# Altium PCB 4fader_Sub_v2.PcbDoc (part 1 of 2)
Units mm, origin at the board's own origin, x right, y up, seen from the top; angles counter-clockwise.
Board outline 100 x 45 mm, 2 copper layers (Top Layer, Bottom Layer); 98 components, 50 nets, 488 pads, 159 vias.
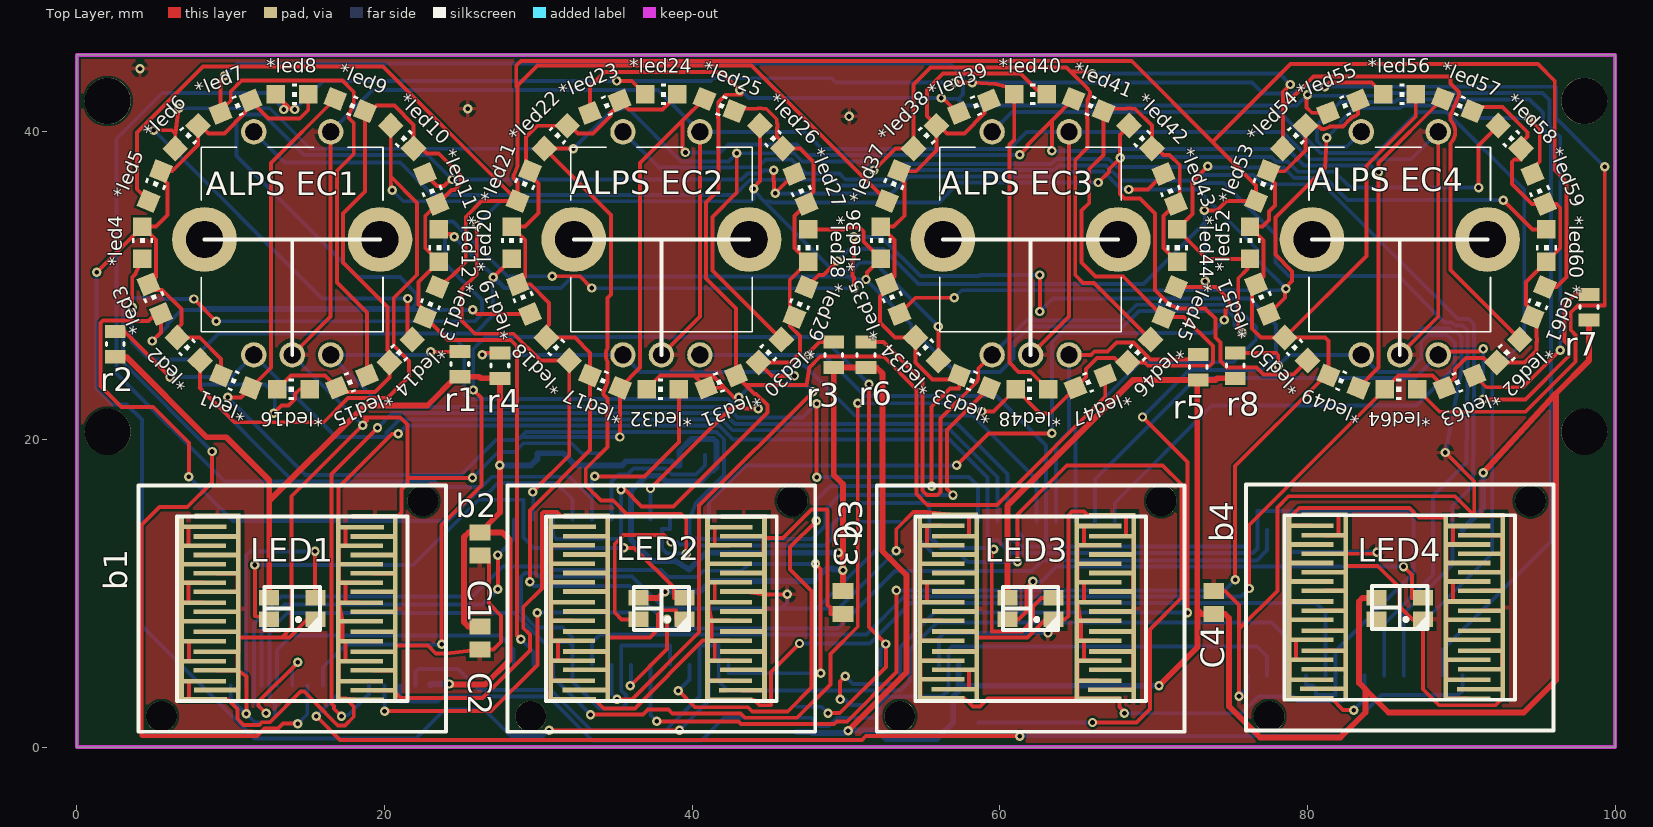
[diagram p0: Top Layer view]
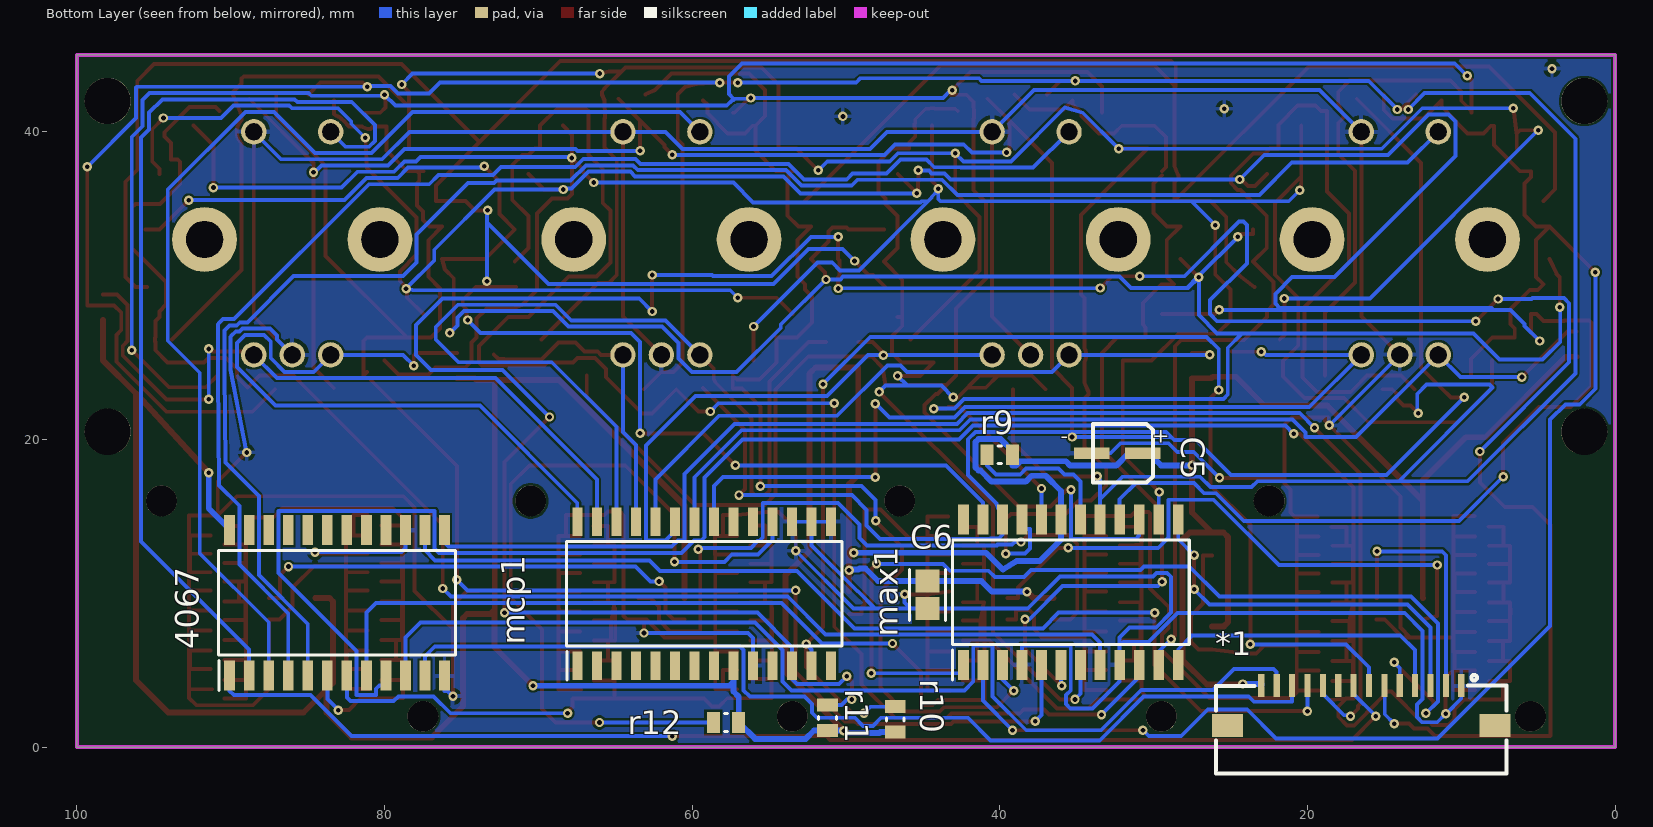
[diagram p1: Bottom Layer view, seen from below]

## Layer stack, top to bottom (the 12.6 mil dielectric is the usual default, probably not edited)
Top Solder: solder mask 0.0102, Solder Resist, Dk 3.5
Top Layer: signal copper 0.0356
Dielectric 1: dielectric 0.32, FR-4, Dk 4.8
Bottom Layer: signal copper 0.0356
Bottom Solder: solder mask 0.0102, Solder Resist, Dk 3.5

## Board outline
0,0 100,0 100,45 0,45

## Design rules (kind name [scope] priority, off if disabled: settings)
Clearance [All] p1: gap=0.152 ignorepadtopadclearanceinfootprint=FALSE
ComponentClearance [All] p1: gap=0.254 collisioncheckmode=3 verticalgap=2540 showdistances=FALSE donotcheckwithout3dbody=TRUE
Height [All] p1: minheight=0 maxheight=254 prefheight=12.7
HoleSize [All] p1: absolutevalues=TRUE maxlimit=25.4 minlimit=0.025 maxpercent=80.000 minpercent=20.000
MinimumSolderMaskSliver [All] p1: minsoldermaskwidth=0.076
PolygonConnect [All] p1: connectstyle=Relief reliefconductorwidth=0.254 reliefentries=4 polygonreliefangle="90 Angle" airgapwidth=0.254
RoutingVias [All] p1: holewidth=0.305 width=0.61 viastyle="Through Hole" minholewidth=0.254 minwidth=0.254 maxholewidth=0.711 maxwidth=1.27
SilkToSilkClearance [All] p1: silktosilkclearance=0
SilkToSolderMaskClearance [IsPad] p1: minsilkscreentomaskgap=0 clearancetoexposedcopper=TRUE
SolderMaskExpansion [All] p1: expansion=0.102 istentingtop=FALSE
SupplyNets "Schematic Supply Nets_1" [InNet('GND')] p1: voltage=0.000
SupplyNets "Schematic Supply Nets" [InNet('+5')] p2: voltage=0.000
Width Width_1 [InNet('+5')] p1: maxlimit=0.508 minlimit=0.254 preferedwidth=0.381
Width [All] p2: maxlimit=0.254 minlimit=0.254 preferedwidth=0.254
24 further rules are at their usual default settings.

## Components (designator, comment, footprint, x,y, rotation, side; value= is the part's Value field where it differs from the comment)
4067 "74HCT4067D,112" SOIC127P1032X265-24N 83.085,9.375 r90 bottom
*1 "trans" FPC-SMD_KH-FG1.0-H2.0-14PIN 16.5,1.586 r180 bottom
*led1 "led1210" 1210贴片led 10.3,23.7 r337.5 top
*led2 "led1210" 1210贴片led 7.213,25.835 r315 top
*led3 "led1210" 1210贴片led 5,29.1 r292.5 top
*led4 "led1210" 1210贴片led 4.2,32.8 r270 top
*led5 "led1210" 1210贴片led 5,36.5 r247.5 top
*led6 "led1210" 1210贴片led 7.1,39.7 r225 top
*led7 "led1210" 1210贴片led 10.3,41.7 r202.5 top
*led8 "led1210" 1210贴片led 14,42.5 r180 top
*led9 "led1210" 1210贴片led 17.8,41.8 r157.5 top
*led10 "led1210" 1210贴片led 21.2,39.7 r135 top
*led11 "led1210" 1210贴片led 23.1,36.3 r112.5 top
*led12 "led1210" 1210贴片led 23.6,32.6 r90 top
*led13 "led1210" 1210贴片led 23.1,28.9 r67.5 top
*led14 "led1210" 1210贴片led 21.1,25.7 r45 top
*led15 "led1210" 1210贴片led 17.9,23.7 r22.5 top
*led16 "led1210" 1210贴片led 14.075,23.2 r0 top
*led17 "led1210" 1210贴片led 34.3,23.7 r337.5 top
*led18 "led1210" 1210贴片led 31.213,25.835 r315 top
*led19 "led1210" 1210贴片led 29,29.1 r292.5 top
*led20 "led1210" 1210贴片led 28.2,32.8 r270 top
*led21 "led1210" 1210贴片led 29,36.5 r247.5 top
*led22 "led1210" 1210贴片led 31.1,39.7 r225 top
*led23 "led1210" 1210贴片led 34.3,41.7 r202.5 top
*led24 "led1210" 1210贴片led 38,42.5 r180 top
*led25 "led1210" 1210贴片led 41.8,41.8 r157.5 top
*led26 "led1210" 1210贴片led 45.2,39.7 r135 top
*led27 "led1210" 1210贴片led 47.1,36.3 r112.5 top
*led28 "led1210" 1210贴片led 47.6,32.6 r90 top
*led29 "led1210" 1210贴片led 47.1,28.9 r67.5 top
*led30 "led1210" 1210贴片led 45.1,25.7 r45 top
*led31 "led1210" 1210贴片led 41.9,23.7 r22.5 top
*led32 "led1210" 1210贴片led 38.075,23.2 r0 top
*led33 "led1210" 1210贴片led 58.3,23.7 r337.5 top
*led34 "led1210" 1210贴片led 55.213,25.835 r315 top
*led35 "led1210" 1210贴片led 53,29.1 r292.5 top
*led36 "led1210" 1210贴片led 52.2,32.8 r270 top
*led37 "led1210" 1210贴片led 53,36.5 r247.5 top
*led38 "led1210" 1210贴片led 55.1,39.7 r225 top
*led39 "led1210" 1210贴片led 58.3,41.7 r202.5 top
*led40 "led1210" 1210贴片led 62,42.5 r180 top
*led41 "led1210" 1210贴片led 65.8,41.8 r157.5 top
*led42 "led1210" 1210贴片led 69.2,39.7 r135 top
*led43 "led1210" 1210贴片led 71.1,36.3 r112.5 top
*led44 "led1210" 1210贴片led 71.6,32.6 r90 top
*led45 "led1210" 1210贴片led 71.1,28.9 r67.5 top
*led46 "led1210" 1210贴片led 69.1,25.7 r45 top
*led47 "led1210" 1210贴片led 65.9,23.7 r22.5 top
*led48 "led1210" 1210贴片led 62.075,23.2 r0 top
*led49 "led1210" 1210贴片led 82.3,23.7 r337.5 top
*led50 "led1210" 1210贴片led 79.213,25.835 r315 top
*led51 "led1210" 1210贴片led 77,29.1 r292.5 top
*led52 "led1210" 1210贴片led 76.2,32.8 r270 top
*led53 "led1210" 1210贴片led 77,36.5 r247.5 top
*led54 "led1210" 1210贴片led 79.1,39.7 r225 top
*led55 "led1210" 1210贴片led 82.3,41.7 r202.5 top
*led56 "led1210" 1210贴片led 86,42.5 r180 top
*led57 "led1210" 1210贴片led 89.8,41.8 r157.5 top
*led58 "led1210" 1210贴片led 93.2,39.7 r135 top
*led59 "led1210" 1210贴片led 95.1,36.3 r112.5 top
*led60 "led1210" 1210贴片led 95.6,32.6 r90 top
*led61 "led1210" 1210贴片led 95.1,28.9 r67.5 top
*led62 "led1210" 1210贴片led 93.1,25.7 r45 top
*led63 "led1210" 1210贴片led 89.9,23.7 r22.5 top
*led64 "led1210" 1210贴片led 86.075,23.2 r0 top
"ALPS EC1" "PEC11H-4125F-S0020" "ALPS EC11" 14,25.5 r0 top
"ALPS EC2" "PEC11H-4125F-S0020" "ALPS EC11" 38,25.5 r0 top
"ALPS EC3" "PEC11H-4125F-S0020" "ALPS EC11" 62,25.5 r0 top
"ALPS EC4" "PEC11H-4125F-S0020" "ALPS EC11" 86,25.5 r0 top
b1 "button" BUTTON 14,9 r180 top
b2 "button" BUTTON 38,9 r180 top
b3 "button" BUTTON 62,9 r180 top
b4 "button" BUTTON 86,9.075 r180 top
C1 "GRM21BR71A106KE51L" CAPC2013X140X45LL15T25 26.2,13.2 r90 top
C2 "GRM21BR71A106KE51L" CAPC2013X140X45LL15T25 26.2,7.1 r270 top
C3 "GRM21BR71A106KE51L" CAPC2013X140X45LL15T25 49.8,9.4 r90 top
C4 "GRM21BR71A106KE51L" CAPC2013X140X45LL15T25 73.9,9.4 r90 top
C5 "10uF" "ELECTROLYTIC CAPACITOR SMD 4X5.4" 34.329,19.1 r90 bottom
C6 "0.1uf" FP-CC0805-0_85-IPC_A 44.7,9.9 r90 bottom value="100 nF"
LED1 "ws2812" ws2812 14,9 r0 top
LED2 "ws2812" ws2812 38,9 r0 top
LED3 "ws2812" ws2812 62,9 r0 top
LED4 "ws2812" ws2812 86,9 r0 top
max1 "MAX7219CWG" SOIC127P1032X265-24N 35.385,10.075 r90 bottom
mcp1 "MCP23017T-E_SO" SOIC127P1030X265-28N 59.215,9.975 r90 bottom
r1 "SG73S2ATTD1101F" RESC2013X60X30LL20T20 24.9,24.9 r270 top
r2 "SG73S2ATTD1101F" RESC2013X60X30LL20T20 2.5,26.2 r270 top
r3 "SG73S2ATTD1101F" RESC2013X60X30LL20T20 49.2,25.5 r270 top
r4 "SG73S2ATTD1101F" RESC2013X60X30LL20T20 27.5,24.8 r270 top
r5 "SG73S2ATTD1101F" RESC2013X60X30LL20T20 72.9,24.7 r270 top
r6 "SG73S2ATTD1101F" RESC2013X60X30LL20T20 51.3,25.5 r270 top
r7 "SG73S2ATTD1101F" RESC2013X60X30LL20T20 98.3,28.6 r270 top
r8 "SG73S2ATTD1101F" RESC2013X60X30LL20T20 75.3,24.8 r270 top
r9 "10k" RESC2013X60X30LL20T20 40,19 r180 bottom
r10 "SG73S2ATTD1101F" RESC2013X60X30LL20T20 46.8,1.8 r270 bottom
r11 "SG73S2ATTD1101F" RESC2013X60X30LL20T20 51.2,1.9 r270 bottom
r12 "SG73S2ATTD1101F" RESC2013X60X30LL20T20 57.8,1.6 r180 bottom

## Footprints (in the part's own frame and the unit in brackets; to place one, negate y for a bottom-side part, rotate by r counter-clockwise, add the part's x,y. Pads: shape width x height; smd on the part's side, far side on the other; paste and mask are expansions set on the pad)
1210贴片led [mm]
  rect 1.2x1.2 smd paste+0 mask+0.051: 1(-1.041,0.064) 2(1.059,0.064)
  silkscreen extent -0.29,-0.61 0.01,0.74, body extent -0.99,-0.56 1.01,0.69, height 0.8
"ALPS EC11" [mm]
  round 1.65 hole 1.1 slot 1.1 at 0 deg paste-2539.97 mask+0.051: A1(-2.5,0) B1(2.5,0) C1(0,0) S1(-2.5,14.5) W1(2.5,14.5)
  round 4.215 hole 2.4 paste-2539.97 mask+0.051: MH1(-5.7,7.5) MH2(5.7,7.5)
  silkscreen extent -5.9,0 5.9,13.5
BUTTON [mm]
  rect 0.3x12 smd paste+0 mask+0.102: 1(-3,0) 1(7.2,0) 2(-6.7,0) 2(3.5,0)
  silkscreen extent -10,-8 10,8
CAPC2013X140X45LL15T25 [mm] "Chip Capacitor, 2-Leads, Body 2.00x1.25mm, IPC High Density"
  rect 1.05x1.35 smd: 1(-0.75,0) 2(0.75,0)
  body extent -1.08,-0.7 1.07,0.7, height 1.4
"ELECTROLYTIC CAPACITOR SMD 4X5.4" [mm]
  rect 0.75x2.3 smd paste+0 mask+0.102: 1(0,-3.629) 2(0,-0.308)
  silkscreen extent -1.91,-4.27 1.9,-0.38
FP-CC0805-0_85-IPC_A [mm]
  rect 1.505x1.556 smd paste+0 mask+0: 1(-0.901,0) 2(0.901,0)
  silkscreen extent -1.65,-1.18 1.65,1.18, body extent -1,-0.63 1,0.63, height 0.95
FPC-SMD_KH-FG1.0-H2.0-14PIN [mm]
  rect 0.4x1.5 smd paste+0 mask+0.05: 1(6.5,2.414) 2(5.5,2.414) 3(4.5,2.414) 4(3.5,2.414) 5(2.5,2.414) 6(1.5,2.414) 7(0.5,2.414) 8(-0.5,2.414) 9(-1.5,2.414) 10(-2.5,2.414) 11(-3.5,2.414) 12(-4.5,2.414) 13(-5.5,2.414) 14(-6.5,2.414)
  rect 2x1.5 smd paste+0 mask+0.05: 15(-8.7,-0.186) 16(8.7,-0.186)
  silkscreen extent -9.46,-3.29 9.45,3.1, body extent -9.53,-2.9 9.53,3.1, height 2
RESC2013X60X30LL20T20 [mm] "Chip Resistor, 2-Leads, Body 2.00x1.25mm, IPC High Density"
  rect 0.85x1.35 smd: 1(-0.825,0) 2(0.825,0)
  silkscreen extent -0.1,-0.57 0.1,0.58, body extent -1.1,-0.72 1.1,0.72, height 0.6
SOIC127P1030X265-28N [mm]
  rect 1.85x0.65 smd: 1(-4.675,8.255) 2(-4.675,6.985) 3(-4.675,5.715) 4(-4.675,4.445) 5(-4.675,3.175) 6(-4.675,1.905) 7(-4.675,0.635) 8(-4.675,-0.635) 9(-4.675,-1.905) 10(-4.675,-3.175) 11(-4.675,-4.445) 12(-4.675,-5.715) 13(-4.675,-6.985) 14(-4.675,-8.255) 15(4.675,-8.255) 16(4.675,-6.985) 17(4.675,-5.715) 18(4.675,-4.445) 19(4.675,-3.175) 20(4.675,-1.905) 21(4.675,-0.635) 22(4.675,0.635) 23(4.675,1.905) 24(4.675,3.175) 25(4.675,4.445) 26(4.675,5.715) 27(4.675,6.985) 28(4.675,8.255)
  silkscreen extent -5.6,-8.95 3.4,8.95, body extent -5.15,-8.95 5.15,8.95, height 2.65
SOIC127P1032X265-24N [mm]
  rect 1.95x0.7 smd: 1(-4.725,6.985) 2(-4.725,5.715) 3(-4.725,4.445) 4(-4.725,3.175) 5(-4.725,1.905) 6(-4.725,0.635) 7(-4.725,-0.635) 8(-4.725,-1.905) 9(-4.725,-3.175) 10(-4.725,-4.445) 11(-4.725,-5.715) 12(-4.725,-6.985) 13(4.725,-6.985) 14(4.725,-5.715) 15(4.725,-4.445) 16(4.725,-3.175) 17(4.725,-1.905) 18(4.725,-0.635) 19(4.725,0.635) 20(4.725,1.905) 21(4.725,3.175) 22(4.725,4.445) 23(4.725,5.715) 24(4.725,6.985)
  silkscreen extent -5.7,-7.7 3.4,7.7, body extent -5.17,-7.7 5.17,7.7, height 2.54
ws2812 [mm]
  rect 1.3x1 smd paste+0 mask+0.102: 1(1.5,-0.7) 2(1.5,0.7) 3(-1.5,0.7) 4(-1.5,-0.7)
  silkscreen extent -1.75,-1.4 1.75,1.4

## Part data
4067: "Integrated Circuit", Manufacturer_Name=Nexperia, Mouser Part Number=771-74HCT4067D
C1 C2 C3 C4: library part CMP-2007-03395-1, Manufacturer=Murata
C5: library part "4.3 X 4.3 ELECTROLYTIC  CAPACITOR SMD μF"
C6: library part CMP-1036-04410-2, "CAP CER 0.1UF 25V X7R 0805", Capacitance="100 nF", Manufacturer=Yageo, Manufacturer Part Number=CC0805KRX7R8BB104, Package=CC0805-0.85, Temperature="-30°C to +85°C", Temperature Characteristic=X7R, Temperature Range High=+85°C, Temperature Range Low=-30°C, Tolerance=0.1, Voltage Rating="25 V"
max1: "Integrated Circuit", Manufacturer_Name="Analog Devices", Mouser Part Number=700-MAX7219CWG-NR
mcp1: "Integrated Circuit", Arrow Part Number=MCP23017T-E/SO, Manufacturer_Name=Microchip, Mouser Part Number=579-MCP23017T-E/SO
r1 r2 r3 r4 r5 r6 r7 r8 r10 r11 r12: library part CMP-2001-02660-1, Manufacturer="KOA Speer"
r9: library part CMP-2001-02660-1, Manufacturer="KOA Speer", Part Number=SG73S2ATTD1101F

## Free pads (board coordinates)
  rect 3x0.3 smd paste+0 mask+0.102: 9(8.249,3.098) 9(18.46,3.073) 9(32.252,3.098) 9(42.438,3.073) 9(56.204,3.175) 9(66.415,3.149) 9(80.207,3.175) 9(90.393,3.149) 10(8.191,4.291) 10(18.391,4.291) 10(32.194,4.317) 10(42.394,4.317) 10(56.204,4.419) 10(66.397,4.317) 10(80.2,4.367) 10(90.4,4.367) 11(8.191,5.591) 11(18.391,5.591) 11(32.194,5.617) 11(42.394,5.617) 11(56.197,5.617) 11(66.397,5.617) 11(80.2,5.667) 11(90.4,5.667) 12(8.191,6.891) 12(18.391,6.891) 12(32.194,6.917) 12(42.394,6.917) 12(56.197,6.917) 12(66.397,6.917) 12(80.2,6.967) 12(90.4,6.967) 13(8.191,8.191) 13(18.391,8.191) 13(32.194,8.217) 13(42.394,8.217) 13(56.197,8.217) 13(66.397,8.217) 13(80.2,8.267) 13(90.4,8.267) 14(8.191,9.391) 14(18.391,9.391) 14(32.194,9.417) 14(42.394,9.417) 14(56.197,9.417) 14(66.397,9.417) 14(80.2,9.467) 14(90.4,9.467) 15(8.191,10.691) 15(18.391,10.691) 15(32.194,10.717) 15(42.394,10.717) 15(56.197,10.717) 15(66.397,10.717) 15(80.2,10.767) 15(90.4,10.767) 16(8.191,11.891) 16(18.391,11.891) 16(32.194,11.917) 16(42.394,11.917) 16(56.197,11.917) 16(66.397,11.917) 16(80.2,11.967) 16(90.4,11.967) 17(8.191,13.091) 17(18.391,13.091) 17(32.194,13.117) 17(42.394,13.117) 17(56.197,13.117) 17(66.397,13.117) 17(80.2,13.167) 17(90.4,13.167) 18(8.242,14.324) 18(18.453,14.299) 18(32.245,14.324) 18(42.43,14.299) 18(56.197,14.4) 18(66.408,14.375) 18(80.2,14.4) 18(90.385,14.375) 19(9.142,15.024) 19(19.353,14.999) 19(33.145,15.024) 19(43.352,14.986) 19(57.097,15.1) 19(67.308,15.075) 19(81.1,15.1) 19(91.307,15.062) 20(9.091,13.691) 20(19.291,13.691) 20(33.094,13.717) 20(43.294,13.717) 20(57.097,13.717) 20(67.297,13.717) 20(81.1,13.767) 20(91.3,13.767) 21(9.091,12.491) 21(19.291,12.491) 21(33.094,12.517) 21(43.294,12.517) 21(57.097,12.517) 21(67.297,12.517) 21(81.1,12.567) 21(91.3,12.567) 22(9.091,11.291) 22(19.291,11.291) 22(33.094,11.317) 22(43.294,11.317) 22(57.097,11.317) 22(67.297,11.317) 22(81.1,11.367) 22(91.3,11.367) 23(9.091,10.091) 23(19.291,10.091) 23(33.094,10.117) 23(43.294,10.117) 23(57.097,10.117) 23(67.297,10.117) 23(81.1,10.167) 23(91.3,10.167) 24(9.091,8.791) 24(19.291,8.791) 24(33.094,8.817) 24(43.294,8.817) 24(57.097,8.817) 24(67.297,8.817) 24(81.1,8.867) 24(91.3,8.867) 25(9.091,7.491) 25(19.291,7.491) 25(33.094,7.517) 25(43.294,7.517) 25(57.097,7.517) 25(67.297,7.517) 25(81.1,7.567) 25(91.3,7.567) 26(9.091,6.191) 26(19.291,6.191) 26(33.094,6.217) 26(43.294,6.217) 26(57.097,6.217) 26(67.297,6.217) 26(81.1,6.267) 26(91.3,6.267) 27(9.091,4.991) 27(9.113,3.708) 27(19.273,3.683) 27(19.291,4.991) 27(33.065,3.708) 27(33.094,5.017) 27(43.25,3.683) 27(43.294,5.017) 27(57.068,3.759) 27(57.097,5.017) 27(67.228,3.733) 27(67.297,5.017) 27(81.02,3.784) 27(81.1,5.067) 27(91.206,3.759) 27(91.3,5.067)
  round 2 hole 2: 28(5.5,2) 28(22.5,16) 28(29.5,2) 28(46.5,16) 28(53.5,2) 28(70.5,16) 28(77.5,2) 28(94.5,16)
  round 3 hole 3: 29(2,20.5) 29(2,42) 29(98,20.5) 29(98,42)

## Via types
v1: diameter 0.61, hole 0.305, Top Layer to Bottom Layer, 159 vias

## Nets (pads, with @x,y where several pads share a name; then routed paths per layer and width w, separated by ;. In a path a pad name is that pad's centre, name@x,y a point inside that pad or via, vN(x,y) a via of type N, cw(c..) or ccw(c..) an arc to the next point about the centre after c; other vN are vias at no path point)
+5: 4067.24 *1.14 C1.2 C2.1 C3.2 C4.1 C5.1 C6.2 LED1.3 LED2.3 LED3.3 LED4.3 max1.19 mcp1.9 r1.2 r2.2 r3.2 r4.2 r5.2 r6.2 r7.2 r8.2 r9.2 r10.2 r11.2 r12.2 | length 323.8
  Top Layer w0.381: r2.2@2.5,25.375 3.2,25.375 8.429,20.146 9.712,20.146 12.51,17.348 12.51,16.015 ; LED1.3@12.5,9.7 12.51,9.7 12.51,16.015 ; v1(24.2,4.1) 24.236,4.064 26.531,4.064 28.131,5.664 28.131,13.475 27.656,13.95 C1.2@26.2,13.95 ; C2.1@26.2,7.85 25.437,7.85 25.159,8.128 25.159,13.645 25.464,13.95 C1.2@26.2,13.95 ; LED2.3@36.5,9.7 37.831,9.7 v1(38.237,10.106) ; v1(49.492,12.636) 49.8,12.636 ; C3.2@49.8,10.15 v1(49.8,11.5) 49.8,12.636 ; v1(50.136,1.067) 53.937,4.869 53.937,11.176 52.363,12.751 52.363,24.294 51.982,24.675 r6.2@51.3,24.675 r3.2@49.2,24.675 49.2,17.694 49.8,17.094 49.8,12.636 ; LED3.3@60.5,9.7 60.491,9.7 60.491,15.697 68.668,23.875 r5.2@72.835,23.875 ; v1(70.346,3.988) 72.848,6.49 72.848,8.928 ; r8.2@75.3,23.975 74.129,23.975 74.029,23.875 r5.2@72.9,23.875 r5.2@72.835,23.875 ; LED4.3@84.5,9.7 83.579,9.7 83.351,9.471 83.351,4.175 83.77,3.756 83.77,3.746 ; v1(91.428,17.831) 96.152,22.98 ; r7.2@98.3,27.775 98.311,27.775 98.311,25.139 96.152,22.98 ; 12.51,16.015 18.707,22.212 22.789,22.212 24.651,24.075 r1.2@24.9,24.075 26.15,24.075 26.25,23.975 r4.2@27.5,23.975 v1(27.5,18.313) 27.5,15.25 C1.2@26.2,13.95 ; r5.2@72.835,23.875 72.835,9.525 72.835,8.941 72.848,8.928 ; 72.848,8.928 73.126,8.65 C4.1@73.9,8.65 74.638,8.65 74.905,8.383 74.905,2.646 76.916,0.635 82.151,0.635 83.77,2.254 83.77,3.746 ; 83.77,3.746 85.266,2.25 94.059,2.25 96.152,4.343 96.152,22.98
  Bottom Layer w0.381: *1.14@23,4 23,4.09 23.009,4.1 v1(24.2,4.1) ; v1(27.5,18.313) 29.528,18.313 29.934,18.72 29.934,19.1 C5.1@30.7,19.1 31.631,19.1 32.436,18.295 35.417,18.295 35.702,18.58 38.672,18.58 38.957,18.295 39.175,18.295 39.175,19.25 39.943,20.018 41.392,20.018 41.593,19.817 41.593,18.183 41.392,17.982 41.262,17.982 40.537,17.258 38.32,17.258 37.938,17.64 37.011,17.64 36.02,16.65 max1.19@36.02,14.8 36.02,13.487 37.417,12.09 38.901,12.09 39.79,11.532 40.895,12.636 v1(49.492,12.636) ; v1(38.237,10.106) 40.504,10.106 41.199,10.801 C6.2@44.7,10.801 47.919,10.801 48.733,11.615 49.114,11.615 49.185,11.544 49.756,11.544 v1(49.8,11.5) ; r10.2@46.8,0.975 47.774,0.975 47.84,0.909 49.978,0.909 v1(50.136,1.067) 50.144,1.075 r11.2@51.2,1.075 52.075,1.075 52.617,0.533 55.908,0.533 r12.2@56.975,1.6 56.975,3.277 57.31,3.612 57.31,4.247 ; mcp1.9@57.31,5.3 57.31,4.247 ; v1(70.346,3.988) 57.57,3.988 57.31,4.247 ; 4067.24@90.07,14.1 90.07,14.148 91.428,15.506 v1(91.428,17.831)
b0: 4067.9 b1.1 pad.9@8.249,3.098 pad.9@18.46,3.073 pad.10@8.191,4.291 pad.10@18.391,4.291 pad.11@8.191,5.591 pad.11@18.391,5.591 pad.12@8.191,6.891 pad.12@18.391,6.891 pad.13@8.191,8.191 pad.13@18.391,8.191 pad.14@8.191,9.391 pad.14@18.391,9.391 pad.15@8.191,10.691 pad.15@18.391,10.691 pad.16@8.191,11.891 pad.16@18.391,11.891 pad.17@8.191,13.091 pad.17@18.391,13.091 pad.18@8.242,14.324 pad.18@18.453,14.299 | length 174.1
  Top Layer w0.254: b1.1@6.8,9 6.818,8.161 b1.1@6.846,6.891 ; pad.10@8.191,4.291 pad.10@7.278,4.291 ; pad.11@8.191,5.591 pad.11@7.278,5.591 ; pad.12@8.191,6.891 pad.12@7.278,6.891 ; pad.13@8.191,8.191 b1.1@6.846,8.191 ; pad.14@8.191,9.391 pad.14@7.252,9.391 ; pad.15@8.191,10.691 pad.15@7.252,10.691 ; pad.16@8.191,11.891 b1.1@6.846,11.891 ; pad.17@8.191,13.091 pad.17@7.252,13.091 ; pad.18@8.242,14.324 7.252,14.324 pad.17@7.252,13.091 ; pad.10@18.391,4.291 17.031,4.291 17.031,5.591 pad.11@17.463,5.591 ; pad.11@18.391,5.591 pad.11@17.463,5.591 ; pad.12@18.391,6.891 pad.12@17.463,6.891 ; pad.13@18.391,8.191 pad.13@17.26,8.191 ; pad.14@18.391,9.391 pad.14@17.463,9.391 ; pad.15@18.391,10.691 pad.15@17.463,10.691 ; pad.16@18.391,11.891 b1.1@17.031,11.891 ; pad.17@18.391,13.091 pad.17@17.463,13.091 ; pad.18@18.453,14.299 17.463,14.299 pad.17@17.463,13.091 ; pad.9@18.46,3.073 pad.9@17.492,3.15 ; v1(20.901,20.361) 20.495,20.361 17,16.866 b1.1@17,9 17,8.191 b1.1@17,6.891 ; b1.1@6.846,6.891 pad.12@7.278,6.891 ; b1.1@6.846,6.891 b1.1@6.846,8.191 ; b1.1@6.846,8.191 6.846,9.391 pad.14@7.252,9.391 ; b1.1@6.846,11.891 6.846,13.091 pad.17@7.252,13.091 ; b1.1@6.846,11.891 6.846,10.691 pad.15@7.252,10.691 ; pad.14@7.252,9.391 pad.15@7.252,10.691 ; pad.10@7.278,4.291 7.278,3.098 pad.9@8.249,3.098 9.818,3.098 10.432,2.484 10.432,1.843 10.828,1.448 11.859,1.448 12.027,1.616 12.542,1.616 14.545,3.619 14.778,3.619 16.142,2.254 16.142,2.232 16.958,1.416 17.442,1.416 18,1.974 18,2.642 pad.9@17.492,3.15 ; pad.10@7.278,4.291 6.846,4.291 6.846,5.591 pad.11@7.278,5.591 ; pad.11@7.278,5.591 pad.12@7.278,6.891 ; b1.1@17,6.891 pad.12@17.26,6.891 ; b1.1@17,6.891 17,5.591 17,4.291 17,3.15 pad.9@17.492,3.15 ; b1.1@17.031,11.891 17.031,10.691 pad.15@17.463,10.691 ; b1.1@17.031,11.891 17.031,13.091 pad.17@17.463,13.091 ; pad.12@17.26,6.891 pad.12@17.463,6.891 ; pad.12@17.26,6.891 pad.13@17.26,8.191 ; pad.13@17.26,8.191 17.102,9.019 17.079,9.141 17.031,9.391 pad.14@17.463,9.391 ; pad.11@17.463,5.591 pad.12@17.463,6.891 ; pad.14@17.463,9.391 pad.15@17.463,10.691
  Bottom Layer w0.254: v1(20.901,20.361) 21.435,20.894 41.755,20.894 42.659,19.99 56.726,19.99 59.195,17.52 59.195,13.64 59.398,13.437 59.891,13.437 60.704,12.624 76.467,12.624 76.741,12.897 76.741,15.354 86.881,15.354 86.901,15.335 86.901,11.328 81.809,6.237 81.809,3.396 80.551,3.396 80.551,3.791 80.328,4.013 79.91,4.013 4067.9@79.91,4.65
b1: 4067.8 b2.1 pad.9@32.252,3.098 pad.9@42.438,3.073 pad.10@32.194,4.317 pad.10@42.394,4.317 pad.11@32.194,5.617 pad.11@42.394,5.617 pad.12@32.194,6.917 pad.12@42.394,6.917 pad.13@32.194,8.217 pad.13@42.394,8.217 pad.14@32.194,9.417 pad.14@42.394,9.417 pad.15@32.194,10.717 pad.15@42.394,10.717 pad.16@32.194,11.917 pad.16@42.394,11.917 pad.17@32.194,13.117 pad.17@42.394,13.117 pad.18@32.245,14.324 pad.18@42.43,14.299 | length 120.1
  Top Layer w0.254: pad.10@32.194,4.317 30.849,4.317 30.849,5.617 pad.11@31.281,5.617 ; pad.11@32.194,5.617 pad.11@31.281,5.617 ; pad.12@32.194,6.917 pad.12@31.281,6.917 ; pad.13@32.194,8.217 b2.1@30.849,8.217 ; pad.14@32.194,9.417 30.849,9.417 b2.1@30.849,8.217 ; pad.15@32.194,10.717 30.849,10.717 b2.1@30.849,11.917 ; pad.16@32.194,11.917 b2.1@30.849,11.917 ; pad.17@32.194,13.117 pad.17@31.179,13.117 ; pad.18@32.245,14.324 30.8,14.324 b2.1@30.8,13.132 ; b2.1@41,9 41,8.217 b2.1@41,6.917 ; pad.10@42.394,4.317 41.034,4.317 41.034,5.617 pad.11@41.466,5.617 ; pad.11@42.394,5.617 pad.11@41.466,5.617 ; pad.12@42.394,6.917 pad.12@41.466,6.917 ; pad.13@42.394,8.217 pad.13@41.263,8.217 ; pad.14@42.394,9.417 pad.14@41.466,9.417 ; pad.15@42.394,10.717 pad.15@41.466,10.717 ; pad.16@42.394,11.917 b2.1@41.034,11.917 ; pad.17@42.394,13.117 pad.17@41.466,13.117 ; pad.18@42.43,14.299 41.466,14.299 pad.17@41.466,13.117 ; v1(46.979,6.731) 45.129,4.882 45.129,2.72 44.385,2.72 44.032,3.073 pad.9@42.438,3.073 41,3.073 b2.1@41,6.917 ; b2.1@30.8,6.917 b2.1@30.849,6.917 ; b2.1@30.8,6.917 30.8,8.217 b2.1@30.8,9 30.8,9.417 30.8,10.717 30.8,11.917 30.8,13.117 b2.1@30.8,13.132 ; b2.1@30.8,6.917 30.8,5.617 30.8,3.608 30.544,3.352 30.798,3.098 pad.9@32.252,3.098 33.668,3.098 34.252,2.515 36.279,2.515 40.681,6.917 b2.1@41,6.917 ; b2.1@30.8,13.132 31.179,13.132 pad.17@31.179,13.117 ; b2.1@30.849,6.917 b2.1@30.849,8.217 ; b2.1@30.849,6.917 pad.12@31.281,6.917 ; b2.1@30.849,11.917 30.849,13.117 pad.17@31.179,13.117 ; pad.11@31.281,5.617 pad.12@31.281,6.917 ; b2.1@41,6.917 pad.12@41.263,6.917 ; b2.1@41.034,11.917 41.034,13.117 pad.17@41.466,13.117 ; b2.1@41.034,11.917 41.034,10.717 pad.15@41.466,10.717 ; pad.12@41.263,6.917 pad.13@41.263,8.217 ; pad.12@41.263,6.917 pad.12@41.466,6.917 ; pad.13@41.263,8.217 41.11,9.021 41.082,9.167 41.034,9.417 pad.14@41.466,9.417 ; pad.11@41.466,5.617 pad.12@41.466,6.917 ; pad.14@41.466,9.417 pad.15@41.466,10.717
  Bottom Layer w0.254: v1(46.979,6.731) 51.55,6.731 54.191,9.373 80.545,9.373 81.18,8.738 4067.8@81.18,4.65
b2: 4067.7 b3.1 pad.9@56.204,3.175 pad.9@66.415,3.149 pad.10@56.204,4.419 pad.10@66.397,4.317 pad.11@56.197,5.617 pad.11@66.397,5.617 pad.12@56.197,6.917 pad.12@66.397,6.917 pad.13@56.197,8.217 pad.13@66.397,8.217 pad.14@56.197,9.417 pad.14@66.397,9.417 pad.15@56.197,10.717 pad.15@66.397,10.717 pad.16@56.197,11.917 pad.16@66.397,11.917 pad.17@56.197,13.117 pad.17@66.397,13.117 pad.18@56.197,14.4 pad.18@66.408,14.375 | length 80.9
  Top Layer w0.254: b3.1@54.8,9 54.8,8.217 b3.1@54.8,6.917 ; pad.11@56.197,5.617 b3.1@54.852,5.617 ; pad.12@56.197,6.917 b3.1@54.852,6.917 ; pad.13@56.197,8.217 b3.1@54.852,8.217 ; pad.14@56.197,9.417 pad.14@55.258,9.417 ; pad.15@56.197,10.717 pad.15@55.258,10.717 ; pad.16@56.197,11.917 b3.1@54.852,11.917 ; pad.17@56.197,13.117 pad.17@55.258,13.117 ; pad.18@56.197,14.4 55.258,14.4 pad.17@55.258,13.117 ; pad.10@56.204,4.419 b3.1@54.852,4.419 ; b3.1@65,9 65,6.917 pad.12@65.266,6.917 ; pad.10@66.397,4.317 b3.1@65.063,4.317 ; pad.11@66.397,5.617 pad.11@65.469,5.617 ; pad.12@66.397,6.917 pad.12@65.469,6.917 ; pad.13@66.397,8.217 pad.13@65.266,8.217 ; pad.14@66.397,9.417 pad.14@65.469,9.417 ; pad.15@66.397,10.717 pad.15@65.469,10.717 ; pad.16@66.397,11.917 b3.1@65.037,11.917 ; pad.17@66.397,13.117 pad.17@65.469,13.117 ; pad.18@66.408,14.375 65.469,14.375 pad.17@65.469,13.117 ; v1(68.1,2.2) 68.1,2.296 67.788,2.608 67.788,3.126 67.765,3.149 b3.1@65.063,3.149 ; b3.1@54.8,6.917 b3.1@54.852,6.917 ; b3.1@54.8,6.917 54.8,5.617 b3.1@54.852,5.617 ; b3.1@54.852,4.419 b3.1@54.852,5.617 ; b3.1@54.852,4.419 54.852,3.175 pad.9@56.204,3.175 57.722,3.175 58.255,2.642 58.712,2.642 59.22,3.149 b3.1@65.063,3.149 ; b3.1@54.852,6.917 b3.1@54.852,8.217 ; b3.1@54.852,8.217 54.852,9.417 pad.14@55.258,9.417 ; b3.1@54.852,11.917 54.852,13.117 pad.17@55.258,13.117 ; b3.1@54.852,11.917 54.852,10.717 pad.15@55.258,10.717 ; pad.14@55.258,9.417 pad.15@55.258,10.717 ; b3.1@65.037,11.917 65.037,13.117 pad.17@65.469,13.117 ; b3.1@65.037,11.917 65.037,10.717 pad.15@65.469,10.717 ; b3.1@65.063,3.149 b3.1@65.063,4.317 ; b3.1@65.063,4.317 65.038,5.59 65.037,5.617 pad.11@65.469,5.617 ; pad.12@65.266,6.917 pad.12@65.469,6.917 ; pad.12@65.266,6.917 pad.13@65.266,8.217 ; pad.13@65.266,8.217 65.113,9.021 65.085,9.167 65.037,9.417 pad.14@65.469,9.417 ; pad.11@65.469,5.617 pad.12@65.469,6.917 ; pad.14@65.469,9.417 pad.15@65.469,10.717
  Bottom Layer w0.254: v1(68.1,2.2) 75.704,2.2 76.806,3.302 79.101,3.302 79.414,2.989 82.216,2.989 82.45,3.223 4067.7@82.45,4.65
b3: 4067.6 b4.1 pad.9@80.207,3.175 pad.9@90.393,3.149 pad.10@80.2,4.367 pad.10@90.4,4.367 pad.11@80.2,5.667 pad.11@90.4,5.667 pad.12@80.2,6.967 pad.12@90.4,6.967 pad.13@80.2,8.267 pad.13@90.4,8.267 pad.14@80.2,9.467 pad.14@90.4,9.467 pad.15@80.2,10.767 pad.15@90.4,10.767 pad.16@80.2,11.967 pad.16@90.4,11.967 pad.17@80.2,13.167 pad.17@90.4,13.167 pad.18@80.2,14.4 pad.18@90.385,14.375 | length 83.4
  Top Layer w0.254: pad.10@80.2,4.367 78.855,4.367 78.855,5.667 pad.11@79.261,5.667 ; pad.11@80.2,5.667 pad.11@79.261,5.667 ; pad.12@80.2,6.967 pad.12@79.261,6.967 ; pad.13@80.2,8.267 b4.1@78.855,8.267 ; pad.14@80.2,9.467 78.855,9.467 b4.1@78.855,8.267 ; pad.15@80.2,10.767 78.855,10.767 b4.1@78.855,11.967 ; pad.16@80.2,11.967 b4.1@78.855,11.967 ; pad.17@80.2,13.167 pad.17@79.185,13.167 ; pad.18@80.2,14.4 b4.1@78.8,14.4 ; v1(83,2.4) 82.982,2.418 82.314,2.418 81.58,3.152 80.23,3.152 pad.9@80.207,3.175 78.8,3.175 78.8,4.367 78.8,5.667 b4.1@78.8,6.967 ; pad.18@90.385,14.375 89.472,14.375 pad.17@89.472,13.167 ; pad.9@90.393,3.149 89,3.149 b4.1@89,5.667 ; pad.10@90.4,4.367 89.04,4.367 b4.1@89.04,5.667 ; pad.11@90.4,5.667 b4.1@89.04,5.667 ; pad.12@90.4,6.967 b4.1@89.04,6.967 ; pad.13@90.4,8.267 b4.1@89.04,8.267 ; pad.14@90.4,9.467 pad.14@89.472,9.467 ; pad.15@90.4,10.767 pad.15@89.472,10.767 ; pad.16@90.4,11.967 b4.1@89.04,11.967 ; pad.17@90.4,13.167 pad.17@89.472,13.167 ; b4.1@78.8,6.967 b4.1@78.8,9.075 78.8,9.467 78.8,10.767 78.8,11.967 78.8,13.167 b4.1@78.8,13.183 ; b4.1@78.8,6.967 b4.1@78.855,6.967 ; b4.1@78.8,13.183 79.185,13.183 pad.17@79.185,13.167 ; b4.1@78.8,13.183 b4.1@78.8,14.4 ; b4.1@78.8,14.4 78.8,14.88 79.465,15.545 86.627,15.545 87.237,14.935 89,14.935 89,11.967 b4.1@89,9.075 89,8.267 b4.1@89,6.967 ; b4.1@78.855,6.967 b4.1@78.855,8.267 ; b4.1@78.855,6.967 pad.12@79.261,6.967 ; b4.1@78.855,11.967 78.855,13.167 pad.17@79.185,13.167 ; pad.11@79.261,5.667 pad.12@79.261,6.967 ; b4.1@89,5.667 b4.1@89.04,5.667 ; b4.1@89,5.667 b4.1@89,6.967 ; b4.1@89,6.967 b4.1@89.04,6.967 ; b4.1@89.04,6.967 b4.1@89.04,8.267 ; b4.1@89.04,8.267 89.04,9.467 pad.14@89.472,9.467 ; b4.1@89.04,11.967 89.04,13.167 pad.17@89.472,13.167 ; b4.1@89.04,11.967 89.04,10.767 pad.15@89.472,10.767 ; pad.14@89.472,9.467 pad.15@89.472,10.767
  Bottom Layer w0.254: v1(83,2.4) 83.72,3.12 4067.6@83.72,4.65
b4: 4067.5 "ALPS EC1.S1" | length 111.9
  Bottom Layer w0.254: 11.5,40 13.501,37.998 21.019,37.998 23.127,35.89 42.764,35.89 43.758,36.884 49.241,36.884 49.626,36.5 52.89,36.5 53.903,37.513 63.54,37.513 63.847,37.821 66.91,37.821 67.901,36.83 72.722,36.83 72.89,36.662 74.578,36.662 77.913,33.327 77.913,31.496 78.796,30.613 85.91,30.613 88.91,27.613 89.41,27.613 89.605,27.417 90.082,27.417 90.342,27.156 90.417,27.082 90.417,25.542 cw(c88.5,25.5) 90.417,25.458 90.417,24.367 90.342,18.5 88.171,16.329 88.171,11.191 84.99,8.01 4067.5@84.99,4.65
b5: 4067.4 "ALPS EC2.S1" | length 86.7
  Bottom Layer w0.254: 35.5,40 37.831,37.668 42.543,37.668 42.572,37.697 44.263,37.697 44.768,38.202 46.454,38.202 47.365,37.291 49.566,37.291 49.951,36.906 52.722,36.906 53.735,37.919 63.371,37.919 63.679,38.227 67.079,38.227 67.602,37.704 72.423,37.704 72.946,37.18 76.504,37.18 77.091,36.592 81.005,36.592 89.774,27.823 90.488,27.823 90.749,27.563 90.823,27.488 90.824,25.501 cw(c88.5,25.5) 90.824,25.495 90.823,24.199 90.749,16.999 89.441,15.691 89.441,11.872 86.26,8.692 4067.4@86.26,4.65
b6: 4067.3 "ALPS EC3.S1" | length 73.8
  Bottom Layer w0.254: 59.5,40 60.793,41.294 78.172,41.294 80.841,38.624 84.51,38.624 87.186,41.3 89.041,41.3 94.095,36.246 94.095,26.416 92.012,24.333 92.012,12.595 87.53,8.113 4067.3@87.53,4.65
b7: 4067.2 "ALPS EC4.S1" | length 59.9
  Bottom Layer w0.254: 83.5,40 82.53,39.031 81.01,39.031 80.633,39.408 80.633,40.437 82.131,41.935 85.666,41.935 85.843,42.113 94.444,42.113 95.307,41.25 95.307,40.139 95.828,39.618 95.828,13.366 88.8,6.338 4067.2@88.8,4.65
c1_1: *led1.2 *led9.2 *led17.2 *led25.2 *led33.2 *led41.2 *led49.2 *led57.2 max1.22 | length 198
  Top Layer w0.254: v1(9.818,22.733) 10.682,22.733 *led1.2@11.303,23.354 12.612,24.662 12.612,37.961 *led9.2@16.797,42.146 ; v1(35.303,20.161) *led17.2@35.303,23.354 36.615,24.665 36.615,37.964 39.383,40.732 ; v1(39.561,38.659) 39.383,38.837 39.383,40.732 ; *led25.2@40.797,42.146 39.383,40.732 ; v1(56.96,16.383) 56.554,16.789 56.554,20.604 *led33.2@59.303,23.354 ; v1(61.303,38.503) 61.804,39.004 61.804,39.153 63.386,40.735 ; v1(63.386,38.76) 63.386,40.735 ; *led41.2@64.797,42.146 63.386,40.735 ; *led49.2@83.303,23.354 84.621,24.671 v1(84.621,37.363) 84.621,37.97 *led57.2@88.797,42.146
  Bottom Layer w0.254: v1(9.818,22.733) 14.865,17.686 24.981,17.686 27.25,19.954 28.658,19.954 28.864,20.161 ; v1(35.303,20.161) 28.864,20.161 ; v1(39.561,38.659) 41.822,38.659 42.347,39.184 46.801,39.184 47.505,38.481 61.281,38.481 v1(61.303,38.503) ; v1(56.96,16.383) 49.619,16.383 48.654,15.418 48.654,14.402 47.791,13.538 40.628,13.538 40.602,13.564 40.069,13.564 39.83,13.803 max1.22@39.83,14.8 40.224,15.839 42.063,17.678 42.063,20.012 41.587,20.488 29.191,20.488 28.864,20.161 ; v1(63.386,38.76) 67.462,38.76 67.588,38.886 78.704,38.886 79.778,37.812 84.099,37.812 84.547,37.363 v1(84.621,37.363)
c1_2: *led2.2 *led10.2 *led18.2 *led26.2 *led34.2 *led42.2 *led50.2 *led58.2 max1.14 | length 191.4
  Top Layer w0.254: *led2.2@8.007,25.131 8.007,23.35 10.241,21.116 16.049,21.116 17.615,22.682 20.181,22.682 21.6,24.101 21.6,25.098 20.6,26.098 20.6,29.198 22.111,30.709 22.111,35.382 20.406,37.087 ; *led10.2@20.406,40.404 20.406,37.087 ; v1(20.5,36.2) 20.432,36.268 20.432,36.606 20.406,36.632 20.406,37.087 ; v1(25.997,33.934) 25.997,30.734 25.007,29.743 25.007,27.737 25.87,26.873 28.385,26.873 30.127,25.131 *led18.2@32.007,25.131 32.007,18.964 v1(29.63,16.586) ; v1(44,36.3) 44,36.396 44.406,36.802 *led26.2@44.406,40.404 ; *led34.2@56.007,25.131 v1(56.007,27.343) ; v1(66.4,36.7) 67.091,37.391 67.091,37.563 v1@67.806,38.278 ; v1@67.806,38.302 67.806,39.804 *led42.2@68.406,40.404 ; v1(67.83,38.302) v1@67.806,38.278 ; *led50.2@80.007,25.131 79.092,24.216 77.153,24.216 76.69,24.679 74.75,24.679 74.334,25.096 74.334,26.315 74.016,26.633 74.016,27.851 73.442,28.426 73.367,28.5 71.609,28.5 71.585,28.524 71.074,28.736 70.092,29.718 70.092,34.687 69.117,35.662 68.111,35.662 67.806,35.966 v1@67.806,38.278 ; v1(91.123,36.373) 91.123,39.121 *led58.2@92.406,40.404
  Bottom Layer w0.254: v1(20.5,36.2) 21.216,35.484 27.547,35.484 ; v1(25.997,33.934) 27.547,35.484 ; v1(29.63,16.586) 29.67,16.546 max1.14@29.67,14.8 ; v1(44,36.3) v1@44,36.15 ; v1(56.007,27.343) 51.855,31.496 50.893,31.496 50.385,30.988 49.162,30.988 44.666,35.484 ; v1(66.4,36.7) 57.323,36.7 56.039,35.416 45.158,35.416 45.09,35.484 44.666,35.484 ; v1(67.83,38.302) 67.882,38.354 77.671,38.354 77.951,38.075 78.702,38.075 79.372,37.405 81.759,37.405 82.792,36.373 v1(91.123,36.373) ; 27.547,35.484 43.851,35.484 44,35.633 v1@44,36.15 ; v1@44,36.15 44.054,36.15 44.427,35.777 44.427,35.723 44.666,35.484
c1_3: *led3.2 *led11.2 *led19.2 *led27.2 *led35.2 *led43.2 *led51.2 *led59.2 max1.16 | length 247.8
  Top Layer w0.254: v1(4.9,26.4) 5.464,26.964 *led3.2@5.464,28.146 5.105,28.146 4.659,27.7 3.32,27.7 3.291,27.729 1.709,27.729 1.537,27.557 1.537,23.47 2.909,22.098 4.966,22.098 7.278,19.787 v1(7.278,17.577) ; *led11.2@22.636,37.254 23.415,36.474 23.878,36.474 24.304,36.9 v1(24.4,36.9) ; v1(25.732,28.422) 26.008,28.146 *led19.2@29.464,28.146 ; v1(45.3,37.5) 45.295,37.495 45.295,36.813 45.332,36.776 45.332,36.068 v1(45.4,36) 45.4,36.009 46.636,37.245 *led27.2@46.636,37.254 ; *led35.2@53.464,28.146 54.528,29.21 v1(57.036,29.21) ; v1(68.39,36.246) 69.627,36.246 *led43.2@70.636,37.254 ; *led51.2@77.464,28.146 78.532,29.214 78.532,29.732 v1(78.6,29.8) 78.6,29.896 79,30.296 79,30.924 77.913,32.012 77.913,34.417 81.143,37.647 v1(81.252,39.615) ; v1(94.374,40.894) 95.1,40.168 95.1,38.06 94.636,37.595 *led59.2@94.636,37.254
  Bottom Layer w0.254: v1(4.9,26.4) 5.881,27.381 5.881,27.509 6.795,28.422 7.902,28.422 ; v1(7.278,17.577) 10.148,14.707 24.143,14.707 25.938,16.501 26.715,16.501 27.384,17.17 31.154,17.17 32.21,16.114 max1.16@32.21,14.8 ; v1(25.732,28.422) 7.902,28.422 ; v1(45.3,37.5) 45.273,37.473 44.614,37.473 44.432,37.291 43.59,37.291 43.199,36.9 v1(24.4,36.9) 22.811,38.489 14.763,38.489 12.129,41.123 10.834,41.123 10.376,40.665 10.376,38.432 18.253,30.556 20.994,30.556 22.086,29.464 22.086,28.829 21.806,28.55 8.03,28.55 7.902,28.422 ; v1(45.4,36) 52.965,36 54.072,37.106 63.708,37.106 64.016,37.414 66.742,37.414 67.842,36.314 68.322,36.314 v1(68.39,36.246) 72.857,36.246 76.77,32.333 76.77,31.63 v1(78.6,29.8) 78.532,29.732 78.201,29.732 78.168,29.699 57.525,29.699 v1(57.036,29.21) ; v1(81.252,39.615) 82.161,40.524 82.161,40.669 83.02,41.529 86.026,41.529 86.203,41.706 89.815,41.706 90.627,40.894 v1(94.374,40.894)
c1_4: *led4.2 *led12.2 *led20.2 *led28.2 *led36.2 *led44.2 *led52.2 *led60.2 max1.20 | length 178.3
  Top Layer w0.254: v1(3.6,28.6) 3.6,30.349 3.597,30.355 3.597,30.527 3.803,30.748 *led4.2@4.264,31.741 ; *led12.2@23.536,33.659 23.536,33.35 24.346,33.35 v1(24.524,33.172) ; v1(27.064,30.541) *led20.2@28.264,31.741 ; v1(37.29,16.815) 42.588,22.113 43.339,22.113 43.452,22 v1(44.3,22) ; *led28.2@47.536,33.659 49.851,33.659 49.968,33.777 50.888,33.777 51.137,33.528 51.137,32.868 *led36.2@52.264,31.741 51.368,30.845 51.368,30.468 v1(51.3,30.4) ; v1(73.521,37.77) 72.53,36.779 72.53,34.653 *led44.2@71.536,33.659 73.454,31.741 *led52.2@76.264,31.741 76.061,31.039 75.5,30.478 75.5,27.251 75.756,26.995 v1(75.756,26.924) ; v1(92.723,35.56) 94.624,33.659 *led60.2@95.536,33.659
  Bottom Layer w0.254: v1(3.6,28.6) 3.569,28.569 3.569,26.34 4.712,25.197 7.506,25.197 9.208,26.899 10.91,26.899 24.245,26.899 ; v1(24.524,33.172) 27.11,30.587 27.846,29.851 ; max1.20@37.29,14.8 v1(37.29,16.815) ; v1(44.3,22) 42.948,22 42.317,22.631 25.464,22.631 25.185,22.911 25.185,25.959 24.245,26.899 ; v1(73.521,37.77) 73.622,37.668 78.474,37.668 79.143,36.999 81.175,36.999 82.614,35.56 v1(92.723,35.56) ; v1(75.756,26.924) 75.265,27.415 75.265,27.929 74.842,28.352 69.053,28.352 68.031,27.33 61.953,27.33 60.895,26.272 60.895,25.271 60.008,24.384 57.112,24.384 54.24,27.256 54.24,27.46 v1(51.3,30.4) 50.367,30.4 50.187,30.58 32.213,30.58 31.484,29.851 27.846,29.851 ; 24.245,26.899 25.87,26.899 27.064,28.092 v1(27.064,30.541) 27.755,29.851 27.846,29.851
